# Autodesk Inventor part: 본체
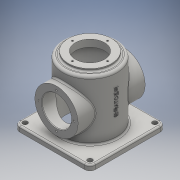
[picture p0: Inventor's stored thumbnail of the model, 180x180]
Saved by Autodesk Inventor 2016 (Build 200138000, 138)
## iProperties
Created: 2019-08
Part Number: 본체
Material: 일반
Document SubType Name: Modeling
Designer: user
Density: 1 g/cm^3
Appearance: 기본값
Author: user
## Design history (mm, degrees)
sketch "스케치1"
  geometry: L1 (60, 70)-(-60, 70); L2 (-70, 60)-(-70, -60); L3 (-60, -70)-(60, -70); L4 (70, -60)-(70, 60); L5 (70, 70)-(-70, -70); L6 (-70, 70)-(70, -70); A1 r 10 centre (-60, 60) between (-60, 70) and (-70, 60); A2 r 10 centre (-60, -60) between (-70, -60) and (-60, -70); A3 r 10 centre (60, -60) between (60, -70) and (70, -60); A4 r 10 centre (60, 60) between (70, 60) and (60, 70); 1 further point
  constraints: 12 end point, 8 point on circle, 8 point on line, 8 tangent, 4 centre point, 3 equal radius, 2 midpoint, 2 parallel, 1 horizontal, 1 perpendicular
  dimensions: "d0" = 140 distance of L5.start L6.start; "d1" = 140 distance of L6.end L5.start; "d2" = 10 radius of A1
extrude "돌출1" new body sketch "스케치1" distance "d3" = 10; taper "d4" = 0 deg
sketch "스케치2"
  geometry: C1 r 50 at (0, 0); 1 further point
  constraints: 1 centre point, 1 coincident
  dimensions: "d5" = 100 diameter of C1
extrude "돌출2" join sketch "스케치2" distance "d6" = 110; taper "d7" = 0 deg
sketch "스케치3"
  geometry: C1 r 40 at (0, 0); 1 further point
  constraints: 1 centre point, 1 coincident
  dimensions: "d8" = 80 diameter of C1
extrude "돌출3" join sketch "스케치3" distance "d9" = 5; taper "d10" = 0 deg
node "작업 평면1"
sketch "스케치4"
  geometry: L1 (-60, 0)-(60, 0) reference; C1 r 40 at (0, 60); 1 further point
  constraints: 1 centre point
  dimensions: "d12" = 80 diameter of C1; "d13" = 60 distance from line of L1 C1.centre
extrude "돌출4" join sketch "스케치4" stored distance "d14" = 5; taper "d15" = 0 deg
sketch "스케치5"
  geometry: C1 r 45 at (0, 0); 1 further point
  constraints: 1 centre point, 1 coincident
  dimensions: "d16" = 90 diameter of C1
extrude "돌출5" cut sketch "스케치5" distance "d17" = 112; taper "d18" = 0 deg
fillet "모깎기1" dims "d19" = 3
fillet "모깎기2" dims "d20" = 3
fillet "모깎기3" dims "d21" = 5
hole "구멍1" diameter "d24" = 54; stored, may be unused: countersink angle "d28" = 90 deg, drill point angle "d30" = 118 deg; dims "d22" = 10, "d23" = 10, "d25" = 6, "d26" = 4, "d27" = 2, "d29" = 8
sketch "스케치6"
  geometry: 2 further points
hole "구멍2" sketch "스케치6" at (0, 32.5) diameter "d32" = 3.242; stored, may be unused: countersink angle "d36" = 82 deg, drill point angle "d38" = 118 deg; dims "d33" = 8, "d34" = 3.023, "d35" = 2, "d37" = 10
hole "구멍3" diameter "d44" = 54; stored, may be unused: countersink angle "d48" = 82 deg, drill point angle "d50" = 0 deg; dims "d42" = 10, "d43" = 10, "d45" = 8, "d46" = 3.023, "d47" = 2, "d49" = 30
sketch "스케치7"
  geometry: 2 further points
hole "구멍4" sketch "스케치7" at (-32.5, 0) diameter "d52" = 3.242; stored, may be unused: countersink angle "d56" = 82 deg, drill point angle "d58" = 118 deg; dims "d53" = 8, "d54" = 3.023, "d55" = 2, "d57" = 10
hole "구멍5" diameter "d64" = 9; stored, may be unused: countersink angle "d68" = 82 deg, drill point angle "d70" = 0 deg; dims "d62" = 10, "d63" = 10, "d65" = 8, "d66" = 3.023, "d67" = 2, "d69" = 10
hole "구멍6" diameter "d73" = 9; stored, may be unused: countersink angle "d77" = 82 deg, drill point angle "d79" = 0 deg; dims "d71" = 10, "d72" = 10, "d74" = 8, "d75" = 3.023, "d76" = 2, "d78" = 10
chamfer "모따기1" distance "d80" = 1; stored, may be unused: second distance "d81" = 2, angle "d82" = 45 deg
fillet "모깎기4" dims "d83" = 3
fillet "모깎기5" dims "d84" = 3
fillet "모깎기6" dims "d85" = 3
node "작업 평면2"
sketch "스케치8"
  geometry: L1 (60, 0)-(-60, 0) reference; 2 further points
  constraints: 1 other
  dimensions: "d87" = 70 distance from line of L1 point (-1.996, 70)
feature "엠보싱1" sketch "스케치8" dims "d0" = 140, "d1" = 140, "d2" = 10, "d88" = 1, "d89" = 0
node "솔리드1"
mirror "대칭1"
pattern_circular "원형 패턴1" dims angle "d40" = 360 deg
mirror "대칭2"
pattern_circular "원형 패턴2" dims angle "d60" = 360 deg
mirror "대칭3"
other parameters: "d11" = -62
